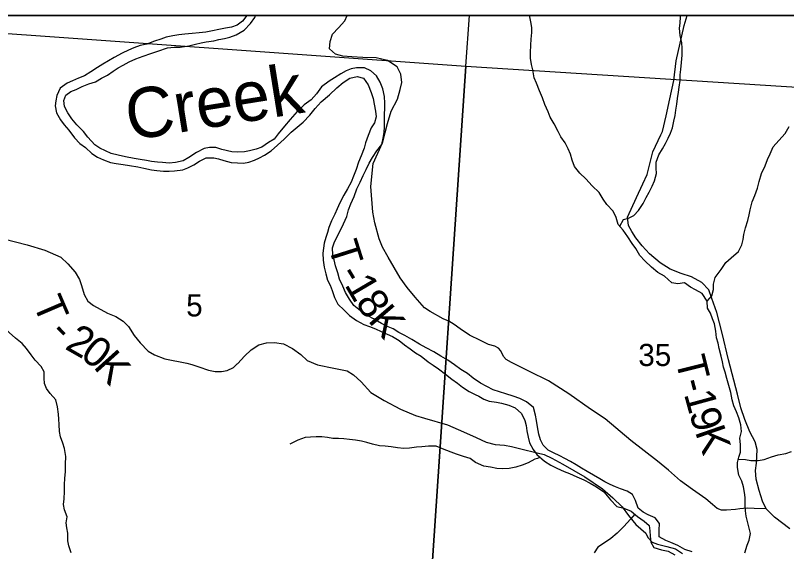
# Model space of a CAD drawing. Extents: x -8.2 to 34, y 0 to 22.
# Drawn here: x 3.755 to 5.214, y 19.885 to 20.9 of the extents above; entities that cross this region are included whole.
import ezdxf

# ---------------------------------------------------------------- set-up
doc = ezdxf.new("R2010")
doc.units = 0
for name, color, linetype in [('GM_X_Corporation', 7, 'Continuous'), ('GM_X_Major_River', 7, 'Continuous'), ('GM_X_Major_River_Text', 7, 'Continuous'), ('GM_X_Minor_River', 7, 'Continuous'), ('GM_X_Section_Text', 7, 'Continuous'), ('GM_X_Township_Road', 7, 'Continuous'), ('GM_X_Township_Road_Text', 7, 'Continuous'), ('SH_Data', 7, 'Continuous')]:
    doc.layers.add(name, color=color, linetype=linetype)

msp = doc.modelspace()

# ---------------------------------------------------------------- linework, layer by layer
at = {"layer": 'GM_X_Corporation'}
msp.add_lwpolyline([(6.4774, 18.0203), (6.488, 18.1752), (6.5242, 18.7061), (6.5297, 18.7882), (6.5448, 18.981), (6.5455, 18.9878), (6.5461, 19.0017), (6.5463, 19.009), (6.5469, 19.0218), (6.548, 19.0467), (6.5487, 19.0617), (6.5495, 19.0821), (6.5503, 19.0966), (6.5514, 19.1092), (6.5523, 19.118), (6.5529, 19.1264), (6.5537, 19.1382), (6.5541, 19.1447), (6.5536, 19.1514), (6.5814, 19.5334), (6.6608, 20.6695), (6.6768, 20.9), (2.1, 20.9), (2.1, 14.1)], dxfattribs=at)
for points in [[(4.614, 20.9), (3.608, 20.9), (3.6063, 20.8752), (4.607, 20.8038)], [(4.607, 20.8038), (4.5379, 19.7849), (3.5308, 19.8461), (3.6063, 20.8752)], [(5.6414, 20.7386), (5.5693, 19.7272), (4.5379, 19.7849), (4.607, 20.8038)]]:
    msp.add_lwpolyline(points, close=True, dxfattribs=at)
at = {"layer": 'GM_X_Major_River'}
for points in [[(4.1927, 20.9), (4.1845, 20.8889), (4.1739, 20.8814), (4.1636, 20.8776), (4.1522, 20.8757), (4.1393, 20.8734), (4.1276, 20.8708), (4.1147, 20.8685), (4.1021, 20.867), (4.0892, 20.8659), (4.0752, 20.8647), (4.0638, 20.8632), (4.0524, 20.8613), (4.0399, 20.8587), (4.0297, 20.8553), (4.0175, 20.8511), (4.0031, 20.8458), (3.9906, 20.8428), (3.9788, 20.8386), (3.9686, 20.8341), (3.9564, 20.8288), (3.9416, 20.8204), (3.9306, 20.814), (3.92, 20.8075), (3.9101, 20.8015), (3.8972, 20.7935), (3.8854, 20.7859), (3.8737, 20.7814), (3.8623, 20.7765), (3.8524, 20.7719), (3.8391, 20.7624), (3.8331, 20.7484), (3.8308, 20.7381), (3.8296, 20.7286), (3.8323, 20.7157), (3.8399, 20.7024), (3.8471, 20.6929), (3.8554, 20.6831), (3.8664, 20.6686), (3.8767, 20.6576), (3.8869, 20.65), (3.8994, 20.639), (3.9097, 20.6317), (3.9214, 20.6264), (3.9347, 20.6215), (3.9449, 20.6199), (3.9582, 20.6176), (3.9707, 20.6161), (3.9863, 20.6134), (3.9977, 20.6108), (4.0121, 20.6081), (4.0223, 20.6066), (4.0345, 20.6054), (4.0455, 20.605), (4.0553, 20.6058), (4.0713, 20.6077), (4.0811, 20.6115), (4.0922, 20.6171), (4.1032, 20.6244), (4.1153, 20.6304), (4.1297, 20.6304), (4.1388, 20.6285), (4.1487, 20.6255), (4.1627, 20.6216), (4.1745, 20.6209), (4.1863, 20.6205), (4.1961, 20.622), (4.2071, 20.6262), (4.2166, 20.6307), (4.2261, 20.6353), (4.2382, 20.644), (4.2504, 20.6546), (4.2629, 20.6656), (4.2766, 20.6789), (4.288, 20.6887), (4.299, 20.6982), (4.3119, 20.7111), (4.3218, 20.724), (4.3328, 20.7362), (4.3487, 20.7498), (4.3628, 20.7631), (4.3749, 20.773), (4.3874, 20.7813), (4.4011, 20.7843), (4.4132, 20.7813), (4.4223, 20.7684), (4.428, 20.7539), (4.4314, 20.7429), (4.4337, 20.7323), (4.436, 20.719), (4.4371, 20.708), (4.4341, 20.697)], [(4.4534, 20.7342), (4.4531, 20.7467), (4.45, 20.7611), (4.4447, 20.774), (4.4379, 20.7858), (4.4269, 20.7953), (4.4148, 20.8006), (4.4, 20.8007), (4.3901, 20.7988), (4.3806, 20.795), (4.3704, 20.7893), (4.3582, 20.7817), (4.3483, 20.7753), (4.3339, 20.7646), (4.3244, 20.7517), (4.3142, 20.7404), (4.3009, 20.7305), (4.288, 20.7184), (4.2743, 20.7032), (4.2637, 20.6903), (4.2519, 20.6762), (4.2439, 20.6656), (4.2333, 20.6596), (4.2208, 20.6508), (4.2102, 20.6467), (4.1976, 20.6436), (4.1878, 20.6421), (4.1741, 20.641), (4.1643, 20.6421), (4.1453, 20.6463), (4.1339, 20.6498), (4.1218, 20.6502), (4.1119, 20.6479), (4.0975, 20.6403), (4.0827, 20.6312), (4.072, 20.6251), (4.0576, 20.6214), (4.0455, 20.6206), (4.033, 20.6214), (4.0235, 20.6225), (4.0121, 20.6233), (4.0026, 20.6252), (3.9909, 20.6275), (3.9791, 20.629), (3.9628, 20.6325), (3.9487, 20.6355), (3.9358, 20.6389), (3.9146, 20.6488), (3.9051, 20.6549), (3.8915, 20.6694), (3.8835, 20.6804), (3.871, 20.6929), (3.8615, 20.7043), (3.8535, 20.7157), (3.8475, 20.7275), (3.846, 20.7389), (3.8501, 20.7488), (3.8596, 20.7563), (3.8695, 20.7601), (3.8809, 20.7654), (3.8938, 20.7704), (3.9059, 20.7745), (3.9173, 20.7813), (3.9287, 20.7867), (3.9393, 20.7942), (3.9492, 20.8007), (3.9587, 20.806), (3.9701, 20.8124), (3.9822, 20.8181), (3.9963, 20.823), (4.0111, 20.828), (4.024, 20.8321), (4.0422, 20.8386), (4.0551, 20.8397), (4.0661, 20.8401), (4.0828, 20.8427), (4.0953, 20.8457), (4.1063, 20.8484), (4.1158, 20.8503), (4.1298, 20.8522), (4.1397, 20.8544), (4.1503, 20.8563), (4.1602, 20.859), (4.1723, 20.8635), (4.1871, 20.8722), (4.1993, 20.8844), (4.2073, 20.8961), (4.2088, 20.9)], [(5.0351, 19.8846), (5.021, 19.8895), (5.0077, 19.8971), (4.9949, 19.9028), (4.9854, 19.9063), (4.9728, 19.9135), (4.9725, 19.926), (4.9736, 19.9382), (4.9653, 19.9492), (4.952, 19.9549), (4.9421, 19.9598), (4.9327, 19.9678), (4.9281, 19.9819), (4.922, 19.9937), (4.9122, 19.9994), (4.8997, 20.0043), (4.8898, 20.0081), (4.8799, 20.0123), (4.8697, 20.0172), (4.8602, 20.023), (4.8485, 20.0298), (4.8363, 20.037), (4.8257, 20.0435), (4.8158, 20.0496), (4.8048, 20.0557), (4.7942, 20.0617), (4.7847, 20.0667), (4.773, 20.072), (4.7627, 20.0773), (4.7529, 20.0868), (4.7483, 20.0971), (4.7449, 20.1077), (4.7426, 20.1214), (4.7407, 20.1332), (4.7385, 20.1438), (4.7347, 20.1579), (4.7218, 20.1685), (4.7093, 20.175), (4.6964, 20.1792), (4.6827, 20.1837), (4.6706, 20.1875), (4.6584, 20.1917), (4.6349, 20.2039), (4.6209, 20.2138), (4.6099, 20.2222), (4.5977, 20.2301), (4.5856, 20.2389), (4.5727, 20.2473), (4.5598, 20.2549), (4.5462, 20.2636), (4.5321, 20.2708), (4.5192, 20.2781), (4.5044, 20.2868), (4.4912, 20.2944), (4.4802, 20.3001), (4.4695, 20.3066), (4.4601, 20.3104), (4.4472, 20.3172), (4.4324, 20.326), (4.4225, 20.3309), (4.4073, 20.3412), (4.3952, 20.3511), (4.3865, 20.3629), (4.3793, 20.3754), (4.374, 20.3879), (4.3679, 20.4008), (4.3645, 20.413), (4.3603, 20.4263), (4.3577, 20.4377), (4.3554, 20.4472), (4.3546, 20.4601), (4.3584, 20.4715), (4.3645, 20.4836), (4.3752, 20.5056), (4.3816, 20.5193), (4.385, 20.5318), (4.3892, 20.5436), (4.3957, 20.5576), (4.4006, 20.5721), (4.4071, 20.5846), (4.4128, 20.5971), (4.4181, 20.6085), (4.4242, 20.6206), (4.4302, 20.6313), (4.4386, 20.6438), (4.4477, 20.6556), (4.4507, 20.6677), (4.4523, 20.6791), (4.453, 20.6886), (4.453, 20.7137), (4.4538, 20.7235), (4.4534, 20.7342)], [(4.4341, 20.697), (4.4276, 20.6871), (4.4223, 20.6727), (4.4173, 20.659), (4.4143, 20.6491), (4.4086, 20.6343), (4.404, 20.6222), (4.3991, 20.6085), (4.3945, 20.5956), (4.3896, 20.5842), (4.3828, 20.5717), (4.3759, 20.5596), (4.3687, 20.5451), (4.3634, 20.5341), (4.3588, 20.5239), (4.3528, 20.511), (4.3478, 20.4988), (4.3448, 20.4893), (4.3418, 20.4795), (4.3387, 20.4692), (4.3376, 20.4597), (4.3364, 20.4499), (4.3368, 20.4369), (4.3387, 20.4237), (4.3417, 20.4107), (4.3451, 20.3993), (4.3504, 20.3898), (4.3542, 20.3796), (4.3584, 20.3659), (4.3645, 20.3534), (4.3766, 20.342), (4.3868, 20.3321), (4.4001, 20.3226), (4.4138, 20.3154), (4.4244, 20.3116), (4.4358, 20.307), (4.4468, 20.302), (4.4581, 20.2971), (4.468, 20.2925), (4.4805, 20.2849), (4.4908, 20.2769), (4.5014, 20.2693), (4.5113, 20.2617), (4.5223, 20.2549), (4.5355, 20.2446), (4.545, 20.2382), (4.5553, 20.2309), (4.5685, 20.2211), (4.5803, 20.2119), (4.5909, 20.2039), (4.6008, 20.1967), (4.6133, 20.1884), (4.6243, 20.1827), (4.6313, 20.1792)], [(4.6313, 20.1792), (4.6406, 20.1735), (4.6512, 20.1701), (4.6649, 20.1682), (4.6744, 20.1663), (4.688, 20.1625), (4.7002, 20.1571), (4.7119, 20.1465), (4.7187, 20.1336), (4.721, 20.1237), (4.7225, 20.1138), (4.7248, 20.1017), (4.7271, 20.0914), (4.7343, 20.0785), (4.7415, 20.069), (4.7559, 20.0565), (4.768, 20.0492), (4.779, 20.0431), (4.7927, 20.0367), (4.8029, 20.0329), (4.817, 20.0268), (4.8299, 20.0211), (4.8424, 20.015), (4.8541, 20.0081), (4.8682, 19.9986), (4.8807, 19.9831), (4.8924, 19.9709), (4.9057, 19.9678), (4.9198, 19.9618), (4.9315, 19.9519), (4.944, 19.9427), (4.9535, 19.9348), (4.955, 19.9249), (4.9554, 19.9146), (4.9569, 19.9029), (4.9626, 19.893), (4.977, 19.8884), (4.9895, 19.8861), (5.0024, 19.8789)]]:
    msp.add_lwpolyline(points, dxfattribs=at)
at = {"layer": 'GM_X_Minor_River'}
for points in [[(5.0633, 20.3595), (5.0541, 20.3735), (5.0412, 20.3807), (5.0317, 20.386), (5.0203, 20.3939), (5.0082, 20.392), (4.9965, 20.3939), (4.9828, 20.4068), (4.9703, 20.4136), (4.9582, 20.4235), (4.9457, 20.4356), (4.9362, 20.4458), (4.9286, 20.4591), (4.9218, 20.4686), (4.9131, 20.4811), (4.9047, 20.4933), (4.8952, 20.5042), (4.8911, 20.5175), (4.8857, 20.5297), (4.8736, 20.5422), (4.8664, 20.5524), (4.8592, 20.5649), (4.8456, 20.5774), (4.8338, 20.5907), (4.8228, 20.6013), (4.8122, 20.6142), (4.808, 20.626), (4.8046, 20.6377), (4.8004, 20.6476), (4.7947, 20.6586), (4.7868, 20.6703), (4.7814, 20.6802), (4.7742, 20.6946), (4.7666, 20.7075), (4.7625, 20.7174), (4.7564, 20.7314), (4.7518, 20.7443), (4.7465, 20.7572), (4.7408, 20.772), (4.7363, 20.7818), (4.7336, 20.797), (4.7313, 20.8072), (4.7294, 20.8194), (4.729, 20.83), (4.7298, 20.844), (4.7305, 20.855), (4.7316, 20.8679), (4.732, 20.8774), (4.7301, 20.8877), (4.7278, 20.8971), (4.7266, 20.9)], [(4.898, 20.5011), (4.9051, 20.5137), (4.9149, 20.5164), (4.9248, 20.5213), (4.9335, 20.5308), (4.9422, 20.5441), (4.9482, 20.5555), (4.9535, 20.5653), (4.9592, 20.5767), (4.9641, 20.587), (4.9675, 20.6006), (4.9671, 20.6109), (4.9671, 20.6226), (4.972, 20.6363), (4.9788, 20.6473), (4.9848, 20.6579), (4.9897, 20.6678), (4.9939, 20.6773), (4.9976, 20.6871), (5.0007, 20.6997), (5.0029, 20.7107), (5.0044, 20.7209), (5.0063, 20.7323), (5.0071, 20.7425), (5.0093, 20.7547), (5.0104, 20.7641), (5.0123, 20.777), (5.0127, 20.7873), (5.0134, 20.7975), (5.0149, 20.8108), (5.016, 20.8248), (5.016, 20.8381), (5.0153, 20.8484), (5.0122, 20.862), (5.0114, 20.8757), (5.0122, 20.8851), (5.0133, 20.8973), (5.0139, 20.9)], [(5.1345, 19.883), (5.1394, 19.8974), (5.1432, 19.9069), (5.1455, 19.9198), (5.1424, 19.9323), (5.1397, 19.9426), (5.1371, 19.9521), (5.1359, 19.9623), (5.1352, 19.9744), (5.1351, 19.9877), (5.1344, 19.9972), (5.1321, 20.0082), (5.1291, 20.0188), (5.1237, 20.0302), (5.1207, 20.0446), (5.1207, 20.0541), (5.1233, 20.0643), (5.1267, 20.0738), (5.1267, 20.0882), (5.1256, 20.1), (5.1282, 20.1125), (5.127, 20.125), (5.1232, 20.1387), (5.1187, 20.1501), (5.1141, 20.1614), (5.1111, 20.1728), (5.108, 20.1861), (5.1046, 20.1994), (5.1004, 20.2126), (5.0974, 20.2248), (5.0947, 20.2343), (5.0928, 20.2445), (5.0902, 20.2551), (5.0864, 20.2695), (5.0841, 20.2798), (5.0814, 20.2896), (5.0799, 20.3022), (5.0772, 20.3162), (5.0738, 20.326), (5.07, 20.3363), (5.0643, 20.3458), (5.0632, 20.3594), (5.0722, 20.3693), (5.0752, 20.3814), (5.0756, 20.3917), (5.0786, 20.4042), (5.09, 20.4194), (5.0987, 20.4323), (5.1089, 20.441), (5.1225, 20.4531), (5.1289, 20.4661), (5.1316, 20.4759), (5.1331, 20.4854), (5.1361, 20.4983), (5.1406, 20.512), (5.1429, 20.5226), (5.1451, 20.5324), (5.1489, 20.5472), (5.1534, 20.559), (5.1587, 20.573), (5.1621, 20.5859), (5.1663, 20.6007), (5.1734, 20.6155), (5.1776, 20.6273), (5.1825, 20.6379), (5.1885, 20.6516), (5.1991, 20.663), (5.2112, 20.6766), (5.2184, 20.6899)], [(3.8599, 19.8827), (3.8554, 19.896), (3.8535, 19.9055), (3.8535, 19.9203), (3.8516, 19.9301), (3.8508, 19.9396), (3.8523, 19.9514), (3.8474, 19.9646), (3.8458, 19.9745), (3.8466, 19.9851), (3.8477, 19.9988), (3.8473, 20.0117), (3.848, 20.0242), (3.8492, 20.036), (3.8495, 20.0511), (3.8499, 20.0652), (3.8476, 20.0807), (3.8446, 20.0906), (3.8396, 20.1027), (3.8381, 20.1126), (3.8373, 20.1259), (3.8366, 20.1357), (3.8358, 20.1452), (3.8343, 20.1596), (3.8308, 20.1725), (3.8206, 20.1843), (3.8134, 20.1937), (3.8096, 20.2032), (3.8088, 20.2135), (3.8088, 20.2256), (3.8035, 20.2358), (3.7921, 20.2476), (3.7845, 20.2575), (3.7754, 20.2696), (3.7675, 20.2791), (3.755, 20.2893), (3.7307, 20.3105)], [(4.7472, 20.064), (4.7424, 20.0618), (4.7375, 20.0603), (4.7246, 20.0531), (4.7136, 20.0486), (4.7015, 20.0448), (4.689, 20.0429), (4.6762, 20.0421), (4.6655, 20.0425), (4.6534, 20.0448), (4.6409, 20.047), (4.6254, 20.0542), (4.6148, 20.0614), (4.6023, 20.0656), (4.589, 20.0698), (4.5788, 20.0735), (4.5629, 20.08), (4.5504, 20.0849), (4.5364, 20.0849), (4.5239, 20.0838), (4.5133, 20.083), (4.5, 20.0811), (4.4898, 20.0807), (4.4777, 20.0818), (4.4656, 20.0837), (4.4542, 20.0849), (4.4432, 20.0852), (4.43, 20.0886), (4.4194, 20.0917), (4.4095, 20.0943), (4.3982, 20.0962), (4.3868, 20.0973), (4.3758, 20.0988), (4.3656, 20.0996), (4.3554, 20.0996), (4.3448, 20.1015), (4.3342, 20.1026), (4.3239, 20.1026), (4.313, 20.1018), (4.3027, 20.1015), (4.2887, 20.0965), (4.274, 20.0889)], [(5.1223, 20.0603), (5.1358, 20.0598), (5.146, 20.0579), (5.1597, 20.0579), (5.1714, 20.0594), (5.185, 20.0644), (5.1979, 20.0685), (5.2123, 20.0712), (5.2229, 20.075)], [(4.9267, 19.9559), (4.9186, 19.947), (4.9061, 19.9326), (4.8933, 19.9201), (4.8812, 19.9102), (4.8694, 19.9022), (4.8566, 19.8935), (4.8494, 19.8829)]]:
    msp.add_lwpolyline(points, dxfattribs=at)
at = {"layer": 'GM_X_Township_Road'}
for points in [[(5.0546, 19.9895), (5.0357, 20.0028), (5.0128, 20.0193), (4.9905, 20.0394), (4.9696, 20.0566), (4.9189, 20.0954), (4.8704, 20.1364), (4.843, 20.1549), (4.8016, 20.1836), (4.763, 20.2083), (4.7272, 20.2261), (4.6931, 20.2433), (4.6829, 20.2486), (4.6781, 20.2546), (4.6728, 20.2652), (4.6686, 20.27), (4.6615, 20.2738), (4.6497, 20.2773), (4.6344, 20.2846), (4.6137, 20.2952), (4.5962, 20.3071), (4.585, 20.3152), (4.5744, 20.3212), (4.564, 20.3256), (4.5391, 20.3397), (4.5288, 20.3468), (4.5111, 20.3666), (4.4957, 20.3854), (4.4829, 20.4032), (4.4597, 20.4425), (4.4494, 20.4614), (4.4428, 20.4775), (4.4344, 20.5078), (4.4309, 20.5274), (4.4274, 20.5761), (4.4313, 20.6196), (4.4491, 20.6589), (4.4589, 20.6954), (4.4658, 20.719), (4.4776, 20.7417), (4.4826, 20.7595), (4.4855, 20.7733), (4.4836, 20.789), (4.4767, 20.8028), (4.4589, 20.8146), (4.4374, 20.8198), (4.4117, 20.8203), (4.391, 20.8214), (4.3739, 20.8232), (4.3603, 20.8268), (4.3491, 20.8368), (4.3502, 20.8504), (4.3544, 20.8646), (4.3662, 20.8764), (4.378, 20.89), (4.3822, 20.9)], [(5.2202, 19.9284), (5.1907, 19.9504), (5.1749, 19.966), (5.1682, 19.9806), (5.1622, 20.0011), (5.156, 20.0227), (5.1552, 20.0389), (5.1569, 20.0525), (5.158, 20.0784), (5.1543, 20.0928), (5.1445, 20.1118), (5.1347, 20.1353), (5.1271, 20.1571), (5.1212, 20.1833), (5.1039, 20.248), (5.0917, 20.2989), (5.0816, 20.3381), (5.0726, 20.3645), (5.0667, 20.381), (5.0536, 20.3946), (5.034, 20.4054), (5.0146, 20.4114), (4.9935, 20.42), (4.9748, 20.4317), (4.9545, 20.4489), (4.9402, 20.4642), (4.9288, 20.479), (4.921, 20.4913), (4.9149, 20.5027), (4.9129, 20.5184), (4.9298, 20.5554), (4.942, 20.581), (4.95, 20.599), (4.9565, 20.6245), (4.9604, 20.6416), (4.966, 20.6528), (4.9761, 20.6739), (4.979, 20.6805), (4.9859, 20.7101), (4.9927, 20.742), (5.0004, 20.7767), (5.0049, 20.814), (5.0202, 20.8808), (5.0257, 20.9)], [(3.7328, 20.4774), (3.7766, 20.4661), (3.8102, 20.4558), (3.8406, 20.4427), (3.8536, 20.4301), (3.8676, 20.4139), (3.876, 20.4005), (3.8793, 20.389), (3.8849, 20.3719), (3.8919, 20.3593), (3.9024, 20.3509), (3.9289, 20.3367), (3.9443, 20.3303), (3.9587, 20.3213), (3.9684, 20.311), (3.9793, 20.2943), (3.9906, 20.2807), (4.0059, 20.2648), (4.018, 20.2575), (4.0371, 20.2501), (4.0789, 20.2418), (4.0882, 20.2394), (4.1019, 20.235), (4.1197, 20.2289), (4.1326, 20.2262), (4.1443, 20.226), (4.1554, 20.228), (4.1672, 20.2338), (4.1744, 20.2404), (4.1753, 20.2413), (4.188, 20.255), (4.2007, 20.2669), (4.2149, 20.2764), (4.2297, 20.2805), (4.245, 20.2811), (4.2618, 20.2785), (4.2791, 20.2696), (4.2945, 20.2583), (4.3067, 20.247), (4.3262, 20.239), (4.3569, 20.2326), (4.3822, 20.2272), (4.3943, 20.22), (4.4085, 20.2064), (4.4269, 20.1861), (4.4526, 20.1713), (4.483, 20.1548), (4.5118, 20.1429), (4.5287, 20.1379), (4.5721, 20.1254), (4.6026, 20.1122), (4.6267, 20.1015), (4.6454, 20.0924), (4.6623, 20.0877), (4.6797, 20.0865), (4.6931, 20.0844), (4.711, 20.0801), (4.7417, 20.0723), (4.7549, 20.069), (4.7695, 20.0624), (4.7905, 20.0509), (4.8322, 20.027), (4.8656, 20.0038), (4.8849, 19.9869), (4.9026, 19.9698), (4.9147, 19.9535), (4.9287, 19.9367), (4.9472, 19.9202), (4.9514, 19.9118), (4.9592, 19.9031), (4.9697, 19.8992), (4.9872, 19.8951), (5.0038, 19.8908), (5.0168, 19.8817)], [(5.1749, 19.966), (5.1526, 19.967), (5.1394, 19.9677), (5.1251, 19.9662), (5.1169, 19.9653), (5.1001, 19.9637), (5.0904, 19.9639), (5.0823, 19.9666), (5.0739, 19.9743), (5.0609, 19.9851), (5.0546, 19.9895)]]:
    msp.add_lwpolyline(points, dxfattribs=at)
at = {"layer": 'SH_Data'}
msp.add_line((2.1, 20.9), (8.9, 20.9), dxfattribs=at)

# ---------------------------------------------------------------- texts
at = {"layer": 'GM_X_Major_River_Text'}
msp.add_text('Creek', height=0.0947, rotation=9.122, dxfattribs=at).set_placement((3.9708, 20.663))
at = {"layer": 'GM_X_Section_Text'}
for s, height, p in [('5', 0.0419, (4.0777, 20.3303)), ('35', 0.04186, (4.9332, 20.2365))]:
    msp.add_text(s, height=height, rotation=0, dxfattribs=at).set_placement(p)
at = {"layer": 'GM_X_Township_Road_Text'}
for s, rotation, p in [('T', 287.6069, (4.3456, 20.464)), ('-', 301.1629, (4.3645, 20.4101)), ('1', 300.4265, (4.3764, 20.3903)), ('T', 293.2706, (3.7867, 20.3548)), ('8', 304.2835, (4.3964, 20.3566)), ('K', 310.4698, (4.4202, 20.3224)), ('-', 314.958, (3.8166, 20.2965)), ('2', 330.239, (3.8462, 20.27)), ('0', 322.4244, (3.8748, 20.2538)), ('K', 311.8998, (3.9006, 20.2343)), ('T', 284.0695, (5.0028, 20.2488)), ('-', 284.3967, (5.0132, 20.2072)), ('1', 285.3173, (5.0193, 20.1836)), ('9', 286.8387, (5.029, 20.1483)), ('K', 289.1204, (5.0399, 20.1125))]:
    msp.add_text(s, height=0.0568, rotation=rotation, dxfattribs=at).set_placement(p)

doc.saveas('drawing.dxf')
